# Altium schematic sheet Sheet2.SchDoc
size A2
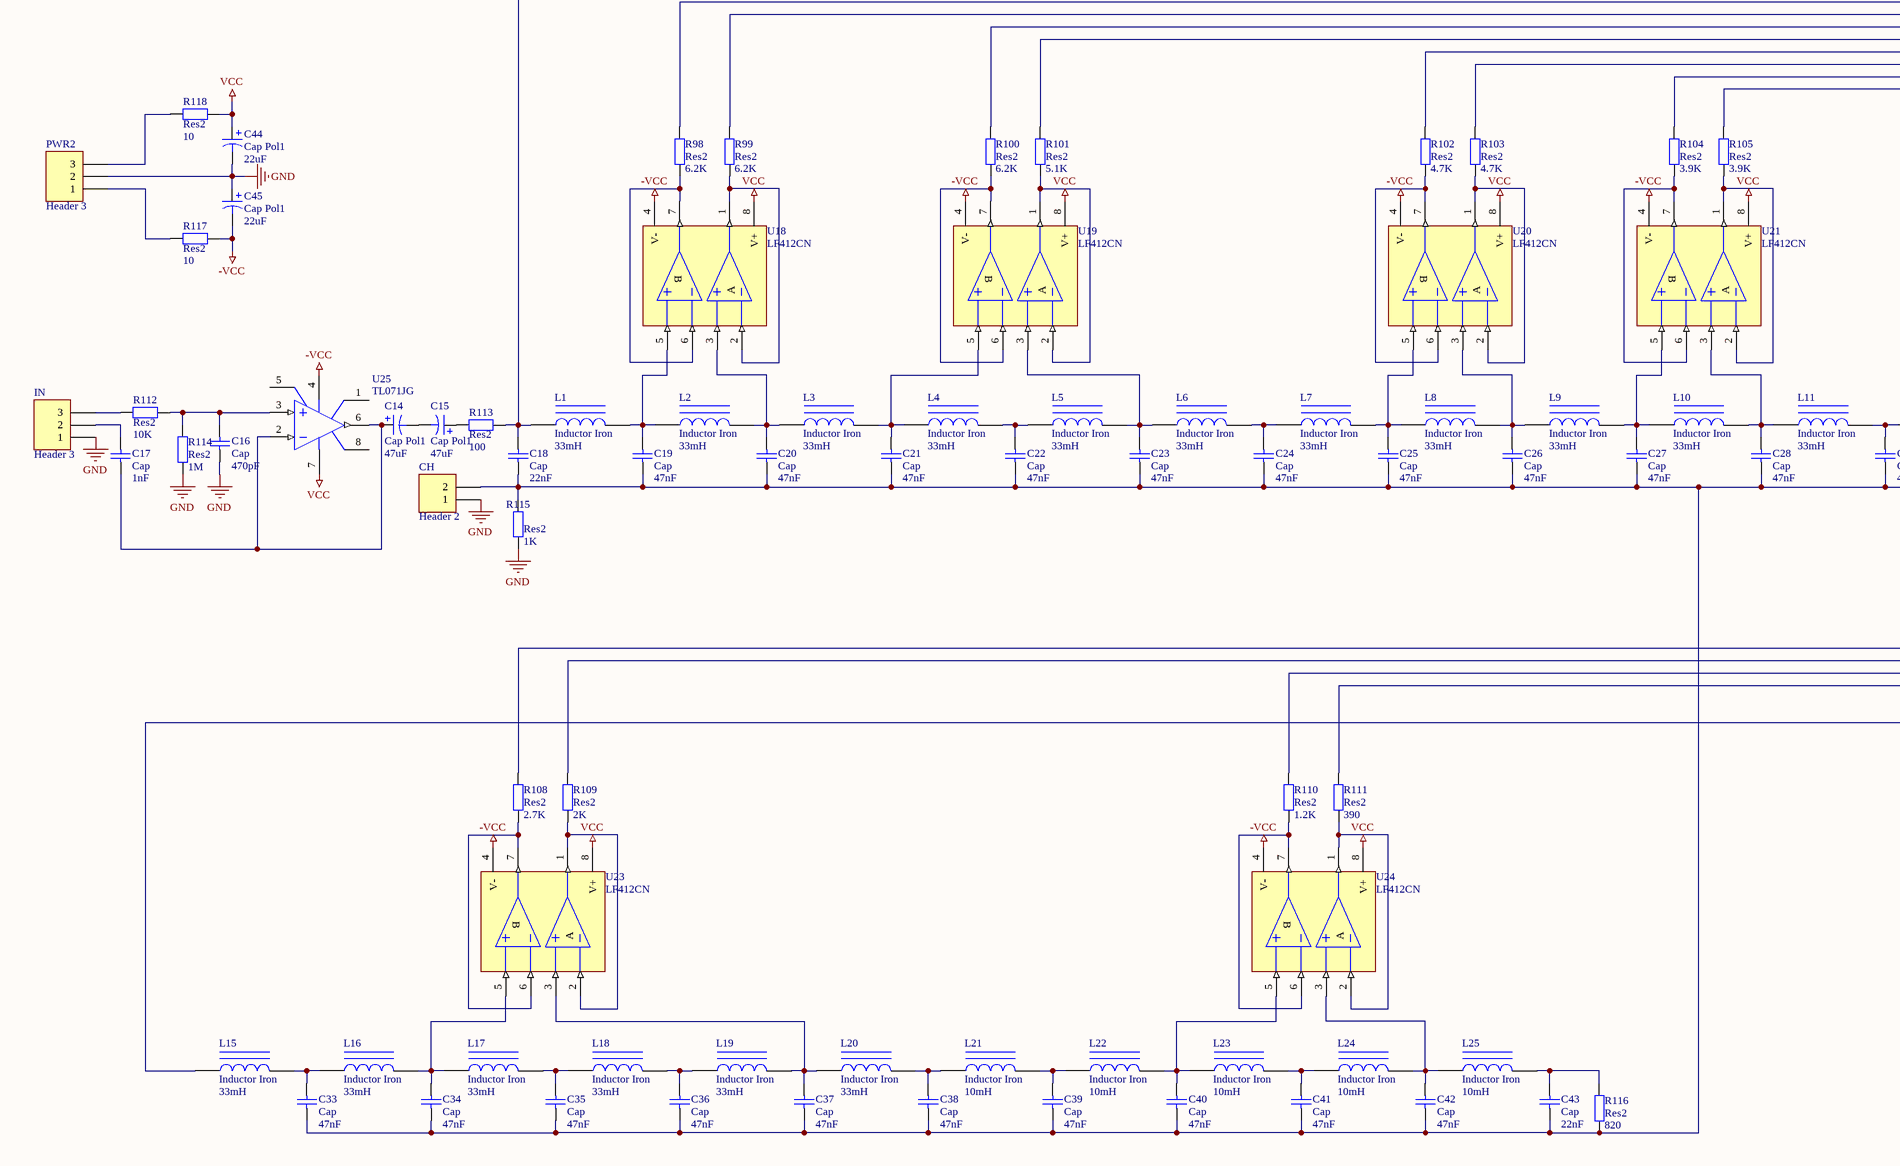
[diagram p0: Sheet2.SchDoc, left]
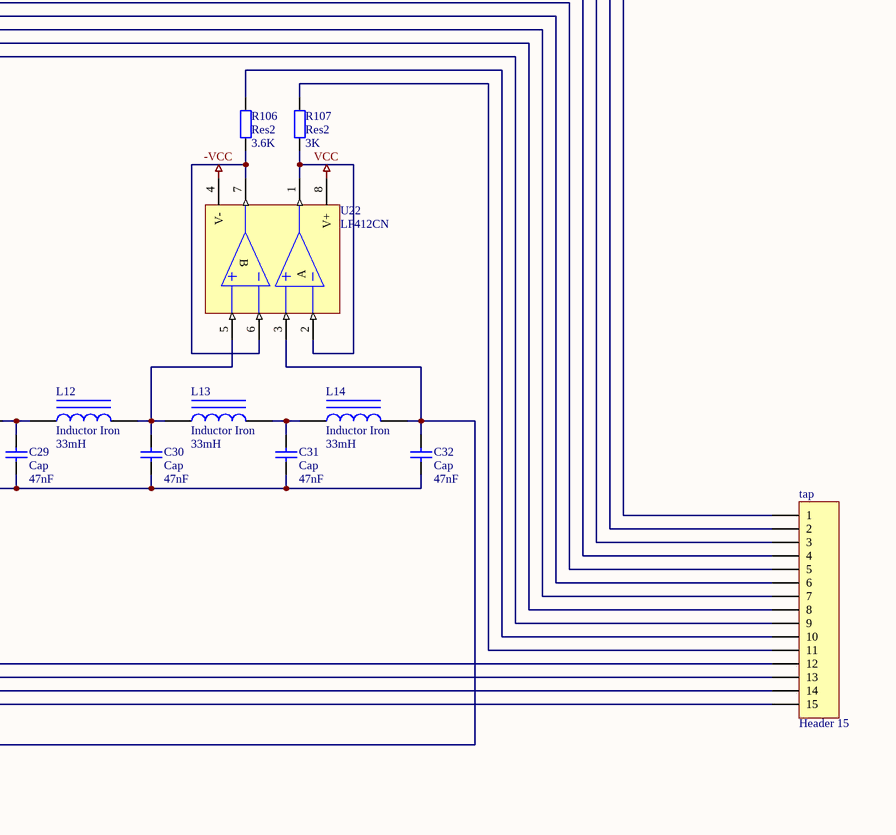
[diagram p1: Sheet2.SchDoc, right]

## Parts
C14  Cap Pol1  value 47uF  [B]
C15  Cap Pol1  value 47uF  [B]
C16  Cap  value 470pF  [VP45-3.2]
C17  Cap  value 1nF  [VP45-3.2]
C18  Cap  value 22nF  [VP45-3.2]
C19  Cap  value 47nF  [VP45-3.2]
C20  Cap  value 47nF  [VP45-3.2]
C21  Cap  value 47nF  [VP45-3.2]
C22  Cap  value 47nF  [VP45-3.2]
C23  Cap  value 47nF  [VP45-3.2]
C24  Cap  value 47nF  [VP45-3.2]
C25  Cap  value 47nF  [VP45-3.2]
C26  Cap  value 47nF  [VP45-3.2]
C27  Cap  value 47nF  [VP45-3.2]
C28  Cap  value 47nF  [VP45-3.2]
C29  Cap  value 47nF  [VP45-3.2]
C30  Cap  value 47nF  [VP45-3.2]
C31  Cap  value 47nF  [VP45-3.2]
C32  Cap  value 47nF  [VP45-3.2]
C33  Cap  value 47nF  [VP45-3.2]
C34  Cap  value 47nF  [VP45-3.2]
C35  Cap  value 47nF  [VP45-3.2]
C36  Cap  value 47nF  [VP45-3.2]
C37  Cap  value 47nF  [VP45-3.2]
C38  Cap  value 47nF  [VP45-3.2]
C39  Cap  value 47nF  [VP45-3.2]
C40  Cap  value 47nF  [VP45-3.2]
C41  Cap  value 47nF  [VP45-3.2]
C42  Cap  value 47nF  [VP45-3.2]
C43  Cap  value 22nF  [VP45-3.2]
C44  Cap Pol1  value 22uF  [B]
C45  Cap Pol1  value 22uF  [B]
CH  Header 2  [HDR1X2]
IN  Header 3  [HDR1X3]
L1  Inductor Iron  value 33mH  [AXIAL-0.9]
L2  Inductor Iron  value 33mH  [AXIAL-0.9]
L3  Inductor Iron  value 33mH  [AXIAL-0.9]
L4  Inductor Iron  value 33mH  [AXIAL-0.9]
L5  Inductor Iron  value 33mH  [AXIAL-0.9]
L6  Inductor Iron  value 33mH  [AXIAL-0.9]
L7  Inductor Iron  value 33mH  [AXIAL-0.9]
L8  Inductor Iron  value 33mH  [AXIAL-0.9]
L9  Inductor Iron  value 33mH  [AXIAL-0.9]
L10  Inductor Iron  value 33mH  [AXIAL-0.9]
L11  Inductor Iron  value 33mH  [AXIAL-0.9]
L12  Inductor Iron  value 33mH  [AXIAL-0.9]
L13  Inductor Iron  value 33mH  [AXIAL-0.9]
L14  Inductor Iron  value 33mH  [AXIAL-0.9]
L15  Inductor Iron  value 33mH  [AXIAL-0.9]
L16  Inductor Iron  value 33mH  [AXIAL-0.9]
L17  Inductor Iron  value 33mH  [AXIAL-0.9]
L18  Inductor Iron  value 33mH  [AXIAL-0.9]
L19  Inductor Iron  value 33mH  [AXIAL-0.9]
L20  Inductor Iron  value 33mH  [AXIAL-0.9]
L21  Inductor Iron  value 10mH  [AXIAL-0.9]
L22  Inductor Iron  value 10mH  [AXIAL-0.9]
L23  Inductor Iron  value 10mH  [AXIAL-0.9]
L24  Inductor Iron  value 10mH  [AXIAL-0.9]
L25  Inductor Iron  value 10mH  [AXIAL-0.9]
PWR2  Header 3  [HDR1X3]
R98  Res2  value 6.2K  [AXIAL-0.4]
R99  Res2  value 6.2K  [AXIAL-0.4]
R100  Res2  value 6.2K  [AXIAL-0.4]
R101  Res2  value 5.1K  [AXIAL-0.4]
R102  Res2  value 4.7K  [AXIAL-0.4]
R103  Res2  value 4.7K  [AXIAL-0.4]
R104  Res2  value 3.9K  [AXIAL-0.4]
R105  Res2  value 3.9K  [AXIAL-0.4]
R106  Res2  value 3.6K  [AXIAL-0.4]
R107  Res2  value 3K  [AXIAL-0.4]
R108  Res2  value 2.7K  [AXIAL-0.4]
R109  Res2  value 2K  [AXIAL-0.4]
R110  Res2  value 1.2K  [AXIAL-0.4]
R111  Res2  value 390  [AXIAL-0.4]
R112  Res2  value 10K  [AXIAL-0.4]
R113  Res2  value 100  [AXIAL-0.4]
R114  Res2  value 1M  [AXIAL-0.4]
R115  Res2  value 1K  [AXIAL-0.4]
R116  Res2  value 820  [AXIAL-0.4]
R117  Res2  value 10  [AXIAL-0.4]
R118  Res2  value 10  [AXIAL-0.4]
tap  Header 15  [HDR1X15]
U18  LF412CN  [N08E]
U19  LF412CN  [N08E]
U20  LF412CN  [N08E]
U21  LF412CN  [N08E]
U22  LF412CN  [N08E]
U23  LF412CN  [N08E]
U24  LF412CN  [N08E]
U25  TL071JG  [JG008]

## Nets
-VCC: C45.2 R117.1 U18.4(V-) U19.4(V-) U20.4(V-) U21.4(V-) U22.4(V-) U23.4(V-) U24.4(V-) U25.4(V-)
GND: C16.1 C44.2 C45.1 CH.1 IN.1 PWR2.2 R114.1 R115.1
VCC: C44.1 R118.1 U18.8(V+) U19.8(V+) U20.8(V+) U21.8(V+) U22.8(V+) U23.8(V+) U24.8(V+) U25.7(V+)
NetC14_1: C14.1 C17.1 U25.2(IN-) U25.6(OUT)
NetC14_2: C14.2 C15.2
NetC15_1: C15.1 R113.1
NetC16_2: C16.2 R112.1 R114.2 U25.3(IN+)
NetC17_2: C17.2 IN.2
NetC18_1: C18.1 C19.1 C20.1 C21.1 C22.1 C23.1 C24.1 C25.1 C26.1 C27.1 C28.1 C29.1 C30.1 C31.1 C32.1 C33.1 C34.1 C35.1 C36.1 C37.1 C38.1 C39.1 C40.1 C41.1 C42.1 C43.1 CH.2 R115.2 R116.1
NetC18_2: C18.2 L1.1 R113.2 tap.1
NetC19_2: C19.2 L1.2 L2.1 U18.5(INB+)
NetC20_2: C20.2 L2.2 L3.1 U18.3(INA+)
NetC21_2: C21.2 L3.2 L4.1 U19.5(INB+)
NetC22_2: C22.2 L4.2 L5.1
NetC23_2: C23.2 L5.2 L6.1 U19.3(INA+)
NetC24_2: C24.2 L6.2 L7.1
NetC25_2: C25.2 L7.2 L8.1 U20.5(INB+)
NetC26_2: C26.2 L8.2 L9.1 U20.3(INA+)
NetC27_2: C27.2 L9.2 L10.1 U21.5(INB+)
NetC28_2: C28.2 L10.2 L11.1 U21.3(INA+)
NetC29_2: C29.2 L11.2 L12.1
NetC30_2: C30.2 L12.2 L13.1 U22.5(INB+)
NetC31_2: C31.2 L13.2 L14.1
NetC32_2: C32.2 L14.2 L15.1 U22.3(INA+)
NetC33_2: C33.2 L15.2 L16.1
NetC34_2: C34.2 L16.2 L17.1 U23.5(INB+)
NetC35_2: C35.2 L17.2 L18.1
NetC36_2: C36.2 L18.2 L19.1
NetC37_2: C37.2 L19.2 L20.1 U23.3(INA+)
NetC38_2: C38.2 L20.2 L21.1
NetC39_2: C39.2 L21.2 L22.1
NetC40_2: C40.2 L22.2 L23.1 U24.5(INB+)
NetC41_2: C41.2 L23.2 L24.1
NetC42_2: C42.2 L24.2 L25.1 U24.3(INA+)
NetC43_2: C43.2 L25.2 R116.2
NetIN_3: IN.3 R112.2
NetPWR2_1: PWR2.1 R117.2
NetPWR2_3: PWR2.3 R118.2
NetR98_1: R98.1 U18.6(INB-) U18.7(OUTB)
NetR98_2: R98.2 tap.2
NetR99_1: R99.1 U18.1(OUTA) U18.2(INA-)
NetR99_2: R99.2 tap.3
NetR100_1: R100.1 U19.6(INB-) U19.7(OUTB)
NetR100_2: R100.2 tap.4
NetR101_1: R101.1 U19.1(OUTA) U19.2(INA-)
NetR101_2: R101.2 tap.5
NetR102_1: R102.1 U20.6(INB-) U20.7(OUTB)
NetR102_2: R102.2 tap.6
NetR103_1: R103.1 U20.1(OUTA) U20.2(INA-)
NetR103_2: R103.2 tap.7
NetR104_1: R104.1 U21.6(INB-) U21.7(OUTB)
NetR104_2: R104.2 tap.8
NetR105_1: R105.1 U21.1(OUTA) U21.2(INA-)
NetR105_2: R105.2 tap.9
NetR106_1: R106.1 U22.6(INB-) U22.7(OUTB)
NetR106_2: R106.2 tap.10
NetR107_1: R107.1 U22.1(OUTA) U22.2(INA-)
NetR107_2: R107.2 tap.11
NetR108_1: R108.1 U23.6(INB-) U23.7(OUTB)
NetR108_2: R108.2 tap.12
NetR109_1: R109.1 U23.1(OUTA) U23.2(INA-)
NetR109_2: R109.2 tap.13
NetR110_1: R110.1 U24.6(INB-) U24.7(OUTB)
NetR110_2: R110.2 tap.14
NetR111_1: R111.1 U24.1(OUTA) U24.2(INA-)
NetR111_2: R111.2 tap.15

Not connected (* = marked no-connect by the designer): U25 1(OS_TRIM) 5(OS_TRIM) 8(NC)

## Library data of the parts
C14 C15 C44 C45 = Cap Pol1: Polarized Capacitor (Radial)
C16-C43 = Cap: Capacitor
CH = Header 2: Header, 2-Pin
IN PWR2 = Header 3: Header, 3-Pin
L1-L25 = Inductor Iron: Magnetic-Core Inductor
R98-R118 = Res2: Resistor
tap = Header 15: Header, 15-Pin
U18-U24 = LF412CN: Low Offset, Low Drift Dual JFET Input Operational Amplifier; Manufacturer: National Semiconductor; CompType: Amplifiers; PackageTopMarking: NSUZXYTT*LF*412CN
U25 = TL071JG: Low-Noise JFET-Input Operational Amplifier; Note: Pin 8 is not connected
